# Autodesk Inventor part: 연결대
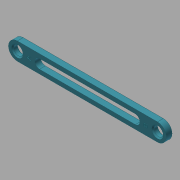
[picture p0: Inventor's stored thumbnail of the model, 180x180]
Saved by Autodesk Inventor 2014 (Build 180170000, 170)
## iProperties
Created: 2017-07
Part Number: 연결대
Material: 스테인리스강
Document SubType Name: Modeling
Designer: mduedu
Density: 8.08 g/cm^3
Appearance: 커뎃 파란색
Mass: 46.8497 g
Surface Area: 49.3916 cm^2
Volume: 5.79823 cm^3
Author: mduedu
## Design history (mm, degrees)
sketch "스케치1"
  geometry: L1 (-67.5, 0)-(67.5, 0); L2 (-67.5, -7.5)-(67.5, -7.5); L3 (67.5, -7.5)-(67.5, 7.5); L4 (67.5, 7.5)-(-67.5, 7.5); L5 (-67.5, 7.5)-(-67.5, -7.5); L6 (-67.5, -7.5)-(67.5, 7.5); L7 (67.5, -7.5)-(-67.5, 7.5); 2 further points
  constraints: 14 end point, 4 midpoint, 2 horizontal, 2 parallel, 1 coincident, 1 perpendicular
  dimensions: "d0" = 135 distance of L1.start L1.end; "d2" = 15 distance of L2.end L3.end
extrude "돌출1" new body sketch "스케치1" distance "d3" = 5; taper "d4" = 0 deg
fillet "모깎기1"
fillet "모깎기2"
sketch "스케치2"
  geometry: C1 r 4 at (60, 0); A1 r 7.5 centre (60, 0) between (60, -7.5) and (60, 7.5) reference; 1 further point
  constraints: 1 centre point, 1 coincident
  dimensions: "d5" = 8 diameter of C1
extrude "돌출2" cut sketch "스케치2" stored distance "d6" = 10; taper "d7" = 0 deg
chamfer "모따기1" distance "d8" = 1; stored, may be unused: second distance "d9" = 2, angle "d10" = 45 deg
sketch "스케치3"
  geometry: L1 (-45, 0)-(45, 0); L2 (-45, -4)-(45, -4); L3 (45, -4)-(45, 4); L4 (45, 4)-(-45, 4); L5 (-45, 4)-(-45, -4); L6 (-45, -4)-(45, 4); L7 (45, -4)-(-45, 4); 2 further points
  constraints: 14 end point, 4 midpoint, 2 horizontal, 2 parallel, 1 coincident, 1 perpendicular
  dimensions: "d11" = 90 distance of L1.start L1.end; "d13" = 8 distance of L2.end L3.end
extrude "돌출3" cut sketch "스케치3" stored distance "d14" = 10; taper "d15" = 0 deg
fillet "모깎기3"
fillet "모깎기4"
sketch "스케치4"
  geometry: L1 (-60, 0)-(60, 0); C1 r 5 at (-60, 0) reference; C2 r 5 at (60, 0) reference; 3 further points
  constraints: 2 end point, 2 point on line, 1 horizontal, 2 other
  dimensions: "d16" = 50 distance of point (-50, 0) point (0, 0); "d17" = 50 distance of point (50, 0) point (0, 0)
feature "엠보싱1" sketch "스케치4" dims "d0" = 135, "d2" = 15, "d18" = 0.5, "d19" = 0
node "솔리드1"
mirror "대칭1"
